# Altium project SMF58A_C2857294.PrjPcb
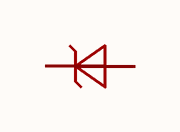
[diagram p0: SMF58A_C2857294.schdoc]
1 sheet, 1 parts. Net scope: global (net labels, ports and power ports of the same name join across sheets).

## Sheet SMF58A_C2857294.schdoc
size 127 x 101 mm

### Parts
D?  smf58a_c2857294  [SOD-123FL_L2.7-W1.8-LS3.7-RD]  (value not drawn)

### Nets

Not connected (* = marked no-connect by the designer): D? 1 2

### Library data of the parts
D? = smf58a_c2857294: 极性:单向;反向截止电压(Vrwm):58V;钳位电压:93.6V;峰值脉冲电流(Ipp):2.1A;峰值脉冲功率(Ppp):200W@10/1000us;击穿电压(VBR):64.4V;; Manufacturer: JSMSEMI(杰盛微); ManufacturerPart: SMF58A; AddInBom: yes; ModelId: 86f9151e155e4fe2af0c4f2e0a80302e; ModelName: SOD-123FL_L2.8-W1.8-H1.1-LS3.6; ModelTransform: 141.732,70.866,0,180,0,0,0,0,0; Polarity: 单向; Reverse Stand-Off Voltage (Vrwm): 58V; Clamping Voltage: 93.6V; Peak Pulse Current (Ipp): 2.1A; Voltage - Breakdown: 64.4V; Reverse Leakage Current (Ir): 1uA; Number of Channels: 单路; Type: TVS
